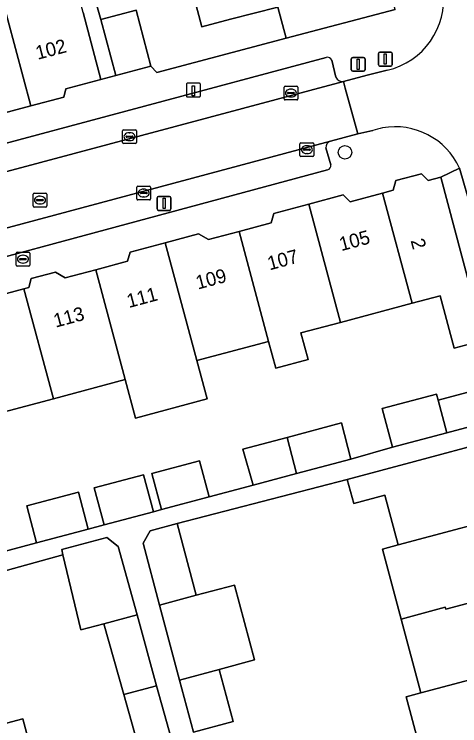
# Model space of a CAD drawing. Extents: x 162542 to 163147, y 380779 to 381521.
# Drawn here: x 162770.6 to 162802.8, y 381019 to 381070.3 of the extents above; entities that cross this region are included whole.
import ezdxf

# ---------------------------------------------------------------- set-up
doc = ezdxf.new("R2010")
doc.units = 0
for name, color, linetype in [('IMGEO_Boom', 7, 'Continuous'), ('IMGEO_Brandkraan', 7, 'Continuous'), ('IMGEO_Erf', 7, 'Continuous'), ('IMGEO_Kolk', 7, 'Continuous'), ('IMGEO_Laadpaal', 7, 'Continuous'), ('IMGEO_Lichtmast', 7, 'Continuous'), ('IMGEO_Muur', 7, 'Continuous'), ('IMGEO_Pand', 7, 'Continuous'), ('IMGEO_Pand_nummerreeks', 7, 'Continuous'), ('IMGEO_Parkeervlak_open', 7, 'Continuous'), ('IMGEO_Rijbaan_lokaal_open', 7, 'Continuous'), ('IMGEO_Rioolput', 7, 'Continuous'), ('IMGEO_Voetpad_open', 7, 'Continuous')]:
    doc.layers.add(name, color=color, linetype=linetype)

msp = doc.modelspace()

# ---------------------------------------------------------------- linework, layer by layer
at = {"layer": 'IMGEO_Boom'}
msp.add_circle((162794.494, 381060.375), 0.489, dxfattribs=at)
at = {"layer": 'IMGEO_Brandkraan'}
for p, q in [((162770.738, 381052.236), (162770.738, 381053.088)), ((162770.813, 381053.162), (162771.665, 381053.162)), ((162771.04, 381052.705), (162771.438, 381052.705)), ((162771.226, 381052.942), (162771.251, 381052.942)), ((162771.739, 381053.088), (162771.739, 381052.236)), ((162770.997, 381052.656), (162770.997, 381052.668)), ((162771.435, 381052.619), (162771.037, 381052.619)), ((162771.249, 381052.382), (162771.224, 381052.382)), ((162771.481, 381052.668), (162771.481, 381052.656)), ((162771.665, 381052.162), (162770.813, 381052.162))]:
    msp.add_line(p, q, dxfattribs=at)
for points in [[(162770.738, 381052.236), (162770.738, 381053.088)], [(162770.813, 381053.162), (162771.665, 381053.162)], [(162771.739, 381053.088), (162771.739, 381052.236)], [(162771.665, 381052.162), (162770.813, 381052.162)]]:
    msp.add_lwpolyline(points, dxfattribs=at)
for centre, radius, start, end in [((162770.815, 381053.086), 0.0765, 91.552, 178.448), ((162770.815, 381053.086), 0.0765, 91.552, 178.448), ((162771.037, 381052.665), 0.0403, 85.8775, 175.7526), ((162771.442, 381052.667), 0.0386, 1.7309, 96.639), ((162771.663, 381053.086), 0.0765, 1.552, 88.448), ((162771.663, 381053.086), 0.0765, 1.552, 88.448), ((162770.815, 381052.238), 0.0765, 181.552, 268.448), ((162770.815, 381052.238), 0.0765, 181.552, 268.448), ((162771.034, 381052.655), 0.0366, 178.938, 274.7102), ((162771.438, 381052.662), 0.043, 264.8664, 352.4533), ((162771.663, 381052.238), 0.0765, 271.552, 358.448), ((162771.663, 381052.238), 0.0765, 271.552, 358.448)]:
    msp.add_arc(centre, radius, start, end, dxfattribs=at)
for centre, major_axis, ratio, start_param, end_param in [((162771.225, 381052.662), (-0.387, 0.002), 0.722429, 4.712389, 7.853982), ((162771.25, 381052.662), (-0.39, 0.002), 0.717154, 1.570796, 4.712389)]:
    msp.add_ellipse(centre, major_axis=major_axis, ratio=ratio, start_param=start_param, end_param=end_param, dxfattribs=at)
at = {"layer": 'IMGEO_Erf'}
for points in [[(162774.056, 381079.887), (162776.859, 381069.965), (162779.405, 381070.644), (162780.482, 381066.606), (162780.903, 381066.133), (162790.25, 381068.607), (162789.654, 381070.857), (162786.215, 381069.993), (162784.155, 381069.446), (162783.526, 381071.816)], [(162804.535, 381046.81), (162802.384, 381046.237), (162801.377, 381050.022), (162799.344, 381049.481), (162794.163, 381048.103), (162791.316, 381047.346), (162791.828, 381045.42), (162789.492, 381044.799), (162788.98, 381046.725), (162783.799, 381045.346), (162784.536, 381042.573), (162779.354, 381041.194), (162778.617, 381043.968), (162773.434, 381042.59), (162768.253, 381041.212)], [(162769.237, 381031.405), (162772.228, 381032.18), (162771.516, 381034.857), (162775.24, 381035.847), (162775.952, 381033.17), (162777.1, 381033.475), (162776.388, 381036.152), (162779.95, 381037.1), (162780.662, 381034.423), (162781.246, 381034.586), (162780.551, 381037.2), (162783.989, 381038.114), (162784.684, 381035.5), (162787.869, 381036.347), (162787.108, 381038.943), (162790.307, 381039.794), (162794.231, 381040.838), (162794.926, 381038.224), (162797.923, 381039.094), (162797.182, 381041.883), (162801.098, 381042.925), (162801.215, 381042.483), (162805.355, 381043.584)], [(162800.284, 381015.954), (162798.917, 381021.069), (162799.976, 381021.363), (162798.554, 381026.681), (162797.202, 381031.738), (162798.325, 381032.038), (162797.365, 381035.632), (162795.127, 381035.034), (162794.663, 381036.768), (162782.37, 381033.574), (162783.755, 381028.398), (162786.521, 381029.138), (162787.967, 381023.733), (162785.414, 381023.049), (162786.42, 381019.291), (162783.558, 381018.525)], [(162779.972, 381016.079), (162778.524, 381021.236), (162777.088, 381026.348), (162775.416, 381025.911), (162774.127, 381031.315), (162765.392, 381028.911), (162766.804, 381023.607), (162768.122, 381018.658), (162771.235, 381019.487), (162772.661, 381014.131)]]:
    msp.add_lwpolyline(points, dxfattribs=at)
at = {"layer": 'IMGEO_Kolk'}
for p, q in [((162790.091, 381064.229), (162790.091, 381065.081)), ((162790.166, 381065.155), (162791.018, 381065.155)), ((162791.092, 381065.081), (162791.092, 381064.229)), ((162790.35, 381064.649), (162790.35, 381064.661)), ((162790.788, 381064.612), (162790.39, 381064.612)), ((162790.393, 381064.698), (162790.791, 381064.698)), ((162790.579, 381064.935), (162790.604, 381064.935)), ((162790.834, 381064.661), (162790.834, 381064.649)), ((162791.018, 381064.155), (162790.166, 381064.155)), ((162790.602, 381064.375), (162790.577, 381064.375)), ((162778.432, 381061.08), (162778.432, 381061.932)), ((162778.507, 381062.006), (162779.359, 381062.006)), ((162779.433, 381061.932), (162779.433, 381061.08)), ((162778.691, 381061.5), (162778.691, 381061.512)), ((162779.129, 381061.463), (162778.731, 381061.463)), ((162778.734, 381061.549), (162779.132, 381061.549)), ((162778.92, 381061.786), (162778.945, 381061.786)), ((162779.175, 381061.512), (162779.175, 381061.5)), ((162779.359, 381061.006), (162778.507, 381061.006)), ((162778.943, 381061.226), (162778.918, 381061.226)), ((162791.241, 381060.143), (162791.241, 381060.995)), ((162791.316, 381061.069), (162792.168, 381061.069)), ((162792.242, 381060.995), (162792.242, 381060.143)), ((162791.5, 381060.563), (162791.5, 381060.575)), ((162791.938, 381060.526), (162791.54, 381060.526)), ((162791.543, 381060.612), (162791.941, 381060.612)), ((162791.729, 381060.849), (162791.754, 381060.849)), ((162791.984, 381060.575), (162791.984, 381060.563)), ((162792.168, 381060.069), (162791.316, 381060.069)), ((162791.752, 381060.289), (162791.727, 381060.289)), ((162779.456, 381057.01), (162779.456, 381057.862)), ((162779.531, 381057.936), (162780.383, 381057.936)), ((162780.457, 381057.862), (162780.457, 381057.01)), ((162779.715, 381057.43), (162779.715, 381057.442)), ((162780.153, 381057.393), (162779.755, 381057.393)), ((162779.758, 381057.479), (162780.156, 381057.479)), ((162779.944, 381057.716), (162779.969, 381057.716)), ((162780.199, 381057.442), (162780.199, 381057.43)), ((162780.383, 381056.936), (162779.531, 381056.936)), ((162779.967, 381057.156), (162779.942, 381057.156))]:
    msp.add_line(p, q, dxfattribs=at)
for points in [[(162790.091, 381064.229), (162790.091, 381065.081)], [(162790.166, 381065.155), (162791.018, 381065.155)], [(162791.092, 381065.081), (162791.092, 381064.229)], [(162791.018, 381064.155), (162790.166, 381064.155)], [(162778.432, 381061.08), (162778.432, 381061.932)], [(162778.507, 381062.006), (162779.359, 381062.006)], [(162779.433, 381061.932), (162779.433, 381061.08)], [(162779.359, 381061.006), (162778.507, 381061.006)], [(162791.241, 381060.143), (162791.241, 381060.995)], [(162791.316, 381061.069), (162792.168, 381061.069)], [(162792.242, 381060.995), (162792.242, 381060.143)], [(162792.168, 381060.069), (162791.316, 381060.069)], [(162779.456, 381057.01), (162779.456, 381057.862)], [(162779.531, 381057.936), (162780.383, 381057.936)], [(162780.457, 381057.862), (162780.457, 381057.01)], [(162780.383, 381056.936), (162779.531, 381056.936)]]:
    msp.add_lwpolyline(points, dxfattribs=at)
for centre, radius, start, end in [((162790.168, 381065.079), 0.0765, 91.552, 178.448), ((162790.168, 381065.079), 0.0765, 91.552, 178.448), ((162791.016, 381065.079), 0.0765, 1.552, 88.448), ((162791.016, 381065.079), 0.0765, 1.552, 88.448), ((162790.39, 381064.658), 0.0403, 85.8775, 175.7526), ((162790.387, 381064.648), 0.0366, 178.938, 274.7102), ((162790.791, 381064.655), 0.043, 264.8664, 352.4533), ((162790.795, 381064.66), 0.0386, 1.7309, 96.639), ((162790.168, 381064.231), 0.0765, 181.552, 268.448), ((162790.168, 381064.231), 0.0765, 181.552, 268.448), ((162791.016, 381064.231), 0.0765, 271.552, 358.448), ((162791.016, 381064.231), 0.0765, 271.552, 358.448), ((162778.509, 381061.93), 0.0765, 91.552, 178.448), ((162778.509, 381061.93), 0.0765, 91.552, 178.448), ((162779.357, 381061.93), 0.0765, 1.552, 88.448), ((162779.357, 381061.93), 0.0765, 1.552, 88.448), ((162778.731, 381061.509), 0.0403, 85.8775, 175.7526), ((162778.728, 381061.499), 0.0366, 178.938, 274.7102), ((162779.132, 381061.506), 0.043, 264.8664, 352.4533), ((162779.136, 381061.511), 0.0386, 1.7309, 96.639), ((162778.509, 381061.082), 0.0765, 181.552, 268.448), ((162778.509, 381061.082), 0.0765, 181.552, 268.448), ((162779.357, 381061.082), 0.0765, 271.552, 358.448), ((162779.357, 381061.082), 0.0765, 271.552, 358.448), ((162791.318, 381060.993), 0.0765, 91.552, 178.448), ((162791.318, 381060.993), 0.0765, 91.552, 178.448), ((162792.166, 381060.993), 0.0765, 1.552, 88.448), ((162792.166, 381060.993), 0.0765, 1.552, 88.448), ((162791.54, 381060.572), 0.0403, 85.8775, 175.7526), ((162791.537, 381060.562), 0.0366, 178.938, 274.7102), ((162791.941, 381060.569), 0.043, 264.8664, 352.4533), ((162791.945, 381060.574), 0.0386, 1.7309, 96.639), ((162791.318, 381060.145), 0.0765, 181.552, 268.448), ((162791.318, 381060.145), 0.0765, 181.552, 268.448), ((162792.166, 381060.145), 0.0765, 271.552, 358.448), ((162792.166, 381060.145), 0.0765, 271.552, 358.448), ((162779.533, 381057.86), 0.0765, 91.552, 178.448), ((162779.533, 381057.86), 0.0765, 91.552, 178.448), ((162780.381, 381057.86), 0.0765, 1.552, 88.448), ((162780.381, 381057.86), 0.0765, 1.552, 88.448), ((162779.755, 381057.439), 0.0403, 85.8775, 175.7526), ((162779.752, 381057.429), 0.0366, 178.938, 274.7102), ((162780.156, 381057.436), 0.043, 264.8664, 352.4533), ((162780.16, 381057.441), 0.0386, 1.7309, 96.639), ((162779.533, 381057.012), 0.0765, 181.552, 268.448), ((162779.533, 381057.012), 0.0765, 181.552, 268.448), ((162780.381, 381057.012), 0.0765, 271.552, 358.448), ((162780.381, 381057.012), 0.0765, 271.552, 358.448)]:
    msp.add_arc(centre, radius, start, end, dxfattribs=at)
for centre, major_axis, ratio, start_param, end_param in [((162790.578, 381064.655), (-0.387, 0.002), 0.722429, 4.712389, 7.853982), ((162790.603, 381064.655), (-0.39, 0.002), 0.717154, 1.570796, 4.712389), ((162778.919, 381061.506), (-0.387, 0.002), 0.722429, 4.712389, 7.853982), ((162778.944, 381061.506), (-0.39, 0.002), 0.717154, 1.570796, 4.712389), ((162791.728, 381060.569), (-0.387, 0.002), 0.722429, 4.712389, 7.853982), ((162791.753, 381060.569), (-0.39, 0.002), 0.717154, 1.570796, 4.712389), ((162779.943, 381057.436), (-0.387, 0.002), 0.722429, 4.712389, 7.853982), ((162779.968, 381057.436), (-0.39, 0.002), 0.717154, 1.570796, 4.712389)]:
    msp.add_ellipse(centre, major_axis=major_axis, ratio=ratio, start_param=start_param, end_param=end_param, dxfattribs=at)
at = {"layer": 'IMGEO_Laadpaal'}
for p, q in [((162783.05, 381065.288), (162783.05, 381064.447)), ((162783.05, 381065.288), (162783.05, 381064.447)), ((162783.966, 381065.372), (162783.125, 381065.372)), ((162783.966, 381065.372), (162783.125, 381065.372)), ((162784.05, 381064.456), (162784.05, 381065.297)), ((162784.05, 381064.456), (162784.05, 381065.297)), ((162783.134, 381064.372), (162783.975, 381064.372)), ((162783.134, 381064.372), (162783.975, 381064.372))]:
    msp.add_line(p, q, dxfattribs=at)
msp.add_lwpolyline([(162783.465, 381065.185), (162783.625, 381065.185), (162783.625, 381064.452), (162783.465, 381064.452), (162783.465, 381065.185)], dxfattribs=at)
for centre, start, end in [((162783.128, 381065.294), 92.4484, 184.2845), ((162783.128, 381065.294), 92.4484, 184.2845), ((162783.972, 381065.294), 2.4484, 94.2845), ((162783.972, 381065.294), 2.4484, 94.2845), ((162783.128, 381064.45), 182.4484, 274.2845), ((162783.128, 381064.45), 182.4484, 274.2845), ((162783.972, 381064.45), 272.4484, 4.2845), ((162783.972, 381064.45), 272.4484, 4.2845)]:
    msp.add_arc(centre, 0.0779, start, end, dxfattribs=at)
at = {"layer": 'IMGEO_Lichtmast'}
for p, q in [((162797.006, 381067.603), (162797.796, 381067.603)), ((162797.796, 381067.603), (162797.006, 381067.603)), ((162794.951, 381066.326), (162794.951, 381067.126)), ((162794.951, 381067.126), (162794.951, 381066.326)), ((162795.051, 381067.226), (162795.841, 381067.226)), ((162795.841, 381067.226), (162795.051, 381067.226)), ((162795.941, 381067.126), (162795.941, 381066.326)), ((162795.941, 381066.326), (162795.941, 381067.126)), ((162796.906, 381066.703), (162796.906, 381067.503)), ((162796.906, 381067.503), (162796.906, 381066.703)), ((162797.896, 381067.503), (162797.896, 381066.703)), ((162797.896, 381066.703), (162797.896, 381067.503)), ((162797.796, 381066.603), (162797.006, 381066.603)), ((162797.006, 381066.603), (162797.796, 381066.603)), ((162795.841, 381066.226), (162795.051, 381066.226)), ((162795.051, 381066.226), (162795.841, 381066.226)), ((162780.932, 381056.288), (162780.932, 381057.088)), ((162780.932, 381057.088), (162780.932, 381056.288)), ((162781.032, 381057.188), (162781.822, 381057.188)), ((162781.822, 381057.188), (162781.032, 381057.188)), ((162781.922, 381057.088), (162781.922, 381056.288)), ((162781.922, 381056.288), (162781.922, 381057.088)), ((162781.822, 381056.188), (162781.032, 381056.188)), ((162781.032, 381056.188), (162781.822, 381056.188))]:
    msp.add_line(p, q, dxfattribs=at)
for points in [[(162795.371, 381067.101), (162795.521, 381067.101), (162795.521, 381066.351), (162795.371, 381066.351), (162795.371, 381067.101)], [(162797.326, 381067.478), (162797.476, 381067.478), (162797.476, 381066.728), (162797.326, 381066.728), (162797.326, 381067.478)], [(162781.352, 381057.063), (162781.502, 381057.063), (162781.502, 381056.313), (162781.352, 381056.313), (162781.352, 381057.063)]]:
    msp.add_lwpolyline(points, dxfattribs=at)
for centre, start, end in [((162797.006, 381067.503), 90, 180), ((162797.006, 381067.503), 90, 180), ((162797.796, 381067.503), 0, 90), ((162797.796, 381067.503), 360, 90), ((162795.051, 381067.126), 90, 180), ((162795.051, 381067.126), 90, 180), ((162795.841, 381067.126), 0, 90), ((162795.841, 381067.126), 360, 90), ((162797.006, 381066.703), 180, 270), ((162797.006, 381066.703), 180, 270), ((162797.796, 381066.703), 270, 0), ((162797.796, 381066.703), 270, 0), ((162795.051, 381066.326), 180, 270), ((162795.051, 381066.326), 180, 270), ((162795.841, 381066.326), 270, 0), ((162795.841, 381066.326), 270, 0), ((162781.032, 381057.088), 90, 180), ((162781.032, 381057.088), 90, 180), ((162781.822, 381057.088), 0, 90), ((162781.822, 381057.088), 360, 90), ((162781.032, 381056.288), 180, 270), ((162781.032, 381056.288), 180, 270), ((162781.822, 381056.288), 270, 0), ((162781.822, 381056.288), 270, 0)]:
    msp.add_arc(centre, 0.1, start, end, dxfattribs=at)
at = {"layer": 'IMGEO_Muur'}
msp.add_lwpolyline([(162790.25, 381068.607), (162780.903, 381066.133), (162780.482, 381066.606)], dxfattribs=at)
at = {"layer": 'IMGEO_Pand'}
for points in [[(162771.805, 381063.723), (162774.182, 381064.357), (162774.346, 381064.969), (162776.867, 381065.641), (162775.579, 381070.473), (162774.793, 381073.421), (162773.82, 381077.07), (162768.611, 381075.681), (162769.584, 381072.032)], [(162796.857, 381075.377), (162789.775, 381073.478), (162789.181, 381073.318), (162788.962, 381073.26), (162783.526, 381071.816), (162784.155, 381069.446), (162786.215, 381069.993), (162789.654, 381070.857), (162790.25, 381068.607), (162798.117, 381070.679)], [(162769.584, 381072.032), (162764.213, 381070.599), (162766.025, 381063.843), (162765.878, 381063.804), (162766.136, 381062.838), (162768.598, 381063.494), (162769.091, 381063), (162771.805, 381063.723)], [(162780.482, 381066.606), (162779.405, 381070.644), (162776.859, 381069.965), (162777.935, 381065.927)], [(162799.344, 381049.481), (162801.377, 381050.022), (162802.384, 381046.237), (162804.535, 381046.81), (162801.405, 381058.58), (162800.504, 381058.341), (162800.018, 381058.829), (162798.163, 381058.335), (162797.974, 381057.636), (162797.213, 381057.434)], [(162794.163, 381048.103), (162799.344, 381049.481), (162797.213, 381057.434), (162794.859, 381056.808), (162794.367, 381057.302), (162791.876, 381056.639)], [(162791.876, 381056.639), (162789.36, 381055.97), (162789.174, 381055.281), (162786.853, 381054.664), (162788.98, 381046.725), (162789.492, 381044.799), (162791.828, 381045.42), (162791.316, 381047.346), (162794.163, 381048.103)], [(162788.98, 381046.725), (162786.853, 381054.664), (162784.629, 381054.072), (162783.91, 381054.49), (162781.519, 381053.854), (162783.799, 381045.346)], [(162778.617, 381043.968), (162779.354, 381041.194), (162784.536, 381042.573), (162783.799, 381045.346), (162781.519, 381053.854), (162778.979, 381053.178), (162778.8, 381052.514), (162776.492, 381051.9)], [(162778.617, 381043.968), (162776.492, 381051.9), (162774.292, 381051.315), (162773.579, 381051.728), (162771.841, 381051.266), (162771.664, 381050.61), (162771.311, 381050.516), (162773.434, 381042.59)], [(162765.984, 381049.682), (162768.253, 381041.212), (162773.434, 381042.59), (162771.311, 381050.516), (162769.04, 381049.912), (162768.58, 381050.373)], [(162801.848, 381040.138), (162805.979, 381041.236), (162805.355, 381043.584), (162801.215, 381042.483)], [(162801.848, 381040.138), (162801.215, 381042.483), (162801.098, 381042.925), (162797.182, 381041.883), (162797.923, 381039.094)], [(162790.307, 381039.794), (162791.002, 381037.18), (162794.926, 381038.224), (162794.231, 381040.838)], [(162798.325, 381032.038), (162807.74, 381034.555), (162806.315, 381039.883), (162801.485, 381038.592), (162799.525, 381038.068), (162794.663, 381036.768), (162795.127, 381035.034), (162797.365, 381035.632)], [(162790.307, 381039.794), (162787.108, 381038.943), (162787.869, 381036.347), (162791.002, 381037.18)], [(162781.246, 381034.586), (162784.684, 381035.5), (162783.989, 381038.114), (162780.551, 381037.2)], [(162777.1, 381033.475), (162780.662, 381034.423), (162779.95, 381037.1), (162776.388, 381036.152)], [(162772.228, 381032.18), (162775.952, 381033.17), (162775.24, 381035.847), (162771.516, 381034.857)], [(162798.554, 381026.681), (162801.73, 381027.542), (162801.769, 381027.398), (162808.109, 381029.095), (162808.147, 381028.951), (162809.165, 381029.223), (162807.74, 381034.555), (162798.325, 381032.038), (162797.202, 381031.738)], [(162782.37, 381033.574), (162780.425, 381033.054), (162779.908, 381032.162), (162781.105, 381027.689), (162783.755, 381028.398)], [(162778.123, 381031.924), (162777.287, 381032.58), (162774.034, 381031.703), (162774.127, 381031.315), (162775.416, 381025.911), (162777.088, 381026.348), (162779.484, 381026.987)], [(162783.755, 381028.398), (162781.105, 381027.689), (162782.552, 381022.284), (162785.414, 381023.049), (162787.967, 381023.733), (162786.521, 381029.138)], [(162798.554, 381026.681), (162799.976, 381021.363), (162809.505, 381023.876), (162808.147, 381028.951), (162808.109, 381029.095), (162801.769, 381027.398), (162801.73, 381027.542)], [(162777.088, 381026.348), (162778.524, 381021.236), (162780.894, 381021.869), (162779.484, 381026.987)], [(162810.868, 381018.786), (162809.505, 381023.876), (162799.976, 381021.363), (162798.917, 381021.069), (162800.284, 381015.954), (162804.097, 381016.973)], [(162785.414, 381023.049), (162782.552, 381022.284), (162783.558, 381018.525), (162786.42, 381019.291)], [(162780.894, 381021.869), (162778.524, 381021.236), (162779.972, 381016.079), (162782.318, 381016.705)], [(162771.235, 381019.487), (162768.122, 381018.658), (162767.564, 381018.509), (162765.096, 381017.852), (162765.147, 381017.666), (162757.964, 381015.749), (162758.011, 381015.58), (162758.966, 381011.993), (162760.394, 381012.373), (162760.77, 381010.962), (162772.661, 381014.131)]]:
    msp.add_lwpolyline(points, close=True, dxfattribs=at)
at = {"layer": 'IMGEO_Parkeervlak_open'}
for points in [[(162793.143, 381067.232), (162766.863, 381060.195)], [(162793.835, 381065.803), (162793.536, 381067.033)], [(162730.046, 381048.353), (162732.138, 381048.912), (162740.764, 381051.202), (162748.957, 381053.378), (162755.459, 381055.104), (162794.388, 381065.492)], [(162793.438, 381061.177), (162749.869, 381049.501)], [(162793.467, 381059.48), (162793.114, 381060.697)], [(162751.104, 381047.757), (162793.241, 381059.11)]]:
    msp.add_lwpolyline(points, dxfattribs=at)
for centre, radius, start, end in [((162793.218, 381066.892), 0.348, 23.9193, 102.3689), ((162794.314, 381066.008), 0.521, 203.1447, 278.1496), ((162793.563, 381060.743), 0.451, 106.0713, 185.89), ((162793.162, 381059.412), 0.313, 284.698, 12.4679)]:
    msp.add_arc(centre, radius, start, end, dxfattribs=at)
at = {"layer": 'IMGEO_Rijbaan_lokaal_open'}
for points in [[(162797.531, 381066.303), (162796.104, 381065.935), (162794.388, 381065.492), (162794.501, 381065.002), (162795.429, 381061.72), (162796.501, 381061.953)], [(162802.766, 381059.241), (162803.658, 381056.146), (162807.705, 381057.197), (162807.647, 381057.415), (162807.233, 381058.879)]]:
    msp.add_lwpolyline(points, dxfattribs=at)
msp.add_lwpolyline([(162793.438, 381061.177), (162795.429, 381061.72), (162794.501, 381065.002), (162794.388, 381065.492), (162755.459, 381055.104), (162748.957, 381053.378), (162749.869, 381049.501)], close=True, dxfattribs=at)
for centre, radius, start, end in [((162796.373, 381071.413), 5.239, 282.7716, 7.263), ((162798.153, 381056.996), 5.226, 100.3561, 108.4338), ((162798.126, 381057.114), 5.104, 24.6286, 100.2933)]:
    msp.add_arc(centre, radius, start, end, dxfattribs=at)
at = {"layer": 'IMGEO_Rioolput'}
for p, q in [((162771.966, 381056.503), (162771.966, 381057.355)), ((162772.041, 381057.429), (162772.893, 381057.429)), ((162772.967, 381057.355), (162772.967, 381056.503)), ((162772.225, 381056.923), (162772.225, 381056.935)), ((162772.663, 381056.886), (162772.265, 381056.886)), ((162772.268, 381056.972), (162772.666, 381056.972)), ((162772.454, 381057.209), (162772.479, 381057.209)), ((162772.709, 381056.935), (162772.709, 381056.923)), ((162772.893, 381056.429), (162772.041, 381056.429)), ((162772.477, 381056.649), (162772.452, 381056.649))]:
    msp.add_line(p, q, dxfattribs=at)
for points in [[(162771.966, 381056.503), (162771.966, 381057.355)], [(162772.041, 381057.429), (162772.893, 381057.429)], [(162772.967, 381057.355), (162772.967, 381056.503)], [(162772.893, 381056.429), (162772.041, 381056.429)]]:
    msp.add_lwpolyline(points, dxfattribs=at)
for centre, radius, start, end in [((162772.043, 381057.353), 0.0765, 91.552, 178.448), ((162772.043, 381057.353), 0.0765, 91.552, 178.448), ((162772.891, 381057.353), 0.0765, 1.552, 88.448), ((162772.891, 381057.353), 0.0765, 1.552, 88.448), ((162772.265, 381056.932), 0.0403, 85.8775, 175.7526), ((162772.262, 381056.922), 0.0366, 178.938, 274.7102), ((162772.666, 381056.929), 0.043, 264.8664, 352.4533), ((162772.67, 381056.934), 0.0386, 1.7309, 96.639), ((162772.043, 381056.505), 0.0765, 181.552, 268.448), ((162772.043, 381056.505), 0.0765, 181.552, 268.448), ((162772.891, 381056.505), 0.0765, 271.552, 358.448), ((162772.891, 381056.505), 0.0765, 271.552, 358.448)]:
    msp.add_arc(centre, radius, start, end, dxfattribs=at)
for centre, major_axis, ratio, start_param, end_param in [((162772.453, 381056.929), (-0.387, 0.002), 0.722429, 4.712389, 7.853982), ((162772.478, 381056.929), (-0.39, 0.002), 0.717154, 1.570796, 4.712389)]:
    msp.add_ellipse(centre, major_axis=major_axis, ratio=ratio, start_param=start_param, end_param=end_param, dxfattribs=at)
at = {"layer": 'IMGEO_Voetpad_open'}
for points in [[(162775.579, 381070.473), (162776.867, 381065.641), (162777.935, 381065.927), (162776.859, 381069.965), (162774.056, 381079.887)], [(162798.117, 381070.679), (162790.25, 381068.607), (162780.903, 381066.133), (162780.482, 381066.606), (162777.935, 381065.927), (162776.867, 381065.641), (162774.346, 381064.969), (162774.182, 381064.357), (162771.805, 381063.723), (162769.091, 381063)], [(162766.863, 381060.195), (162793.143, 381067.232)], [(162793.536, 381067.033), (162793.835, 381065.803)], [(162794.388, 381065.492), (162796.104, 381065.935), (162797.531, 381066.303)], [(162796.501, 381061.953), (162795.429, 381061.72), (162793.438, 381061.177)], [(162793.114, 381060.697), (162793.467, 381059.48)], [(162793.241, 381059.11), (162751.104, 381047.757)], [(162769.04, 381049.912), (162771.311, 381050.516), (162771.664, 381050.61), (162771.841, 381051.266), (162773.579, 381051.728), (162774.292, 381051.315), (162776.492, 381051.9), (162778.8, 381052.514), (162778.979, 381053.178), (162781.519, 381053.854), (162783.91, 381054.49), (162784.629, 381054.072), (162786.853, 381054.664), (162789.174, 381055.281), (162789.36, 381055.97), (162791.876, 381056.639), (162794.367, 381057.302), (162794.859, 381056.808), (162797.213, 381057.434), (162797.974, 381057.636), (162798.163, 381058.335), (162800.018, 381058.829), (162800.504, 381058.341), (162801.405, 381058.58), (162802.766, 381059.241)], [(162803.658, 381056.146), (162802.766, 381059.241), (162801.405, 381058.58), (162804.535, 381046.81)], [(162805.979, 381041.236), (162801.848, 381040.138), (162797.923, 381039.094), (162794.926, 381038.224), (162791.002, 381037.18), (162787.869, 381036.347), (162784.684, 381035.5), (162781.246, 381034.586), (162780.662, 381034.423), (162777.1, 381033.475), (162775.952, 381033.17), (162772.228, 381032.18), (162769.237, 381031.405)], [(162783.558, 381018.525), (162782.552, 381022.284), (162781.105, 381027.689), (162779.908, 381032.162), (162780.425, 381033.054), (162782.37, 381033.574), (162794.663, 381036.768), (162799.525, 381038.068), (162801.485, 381038.592), (162806.315, 381039.883)], [(162765.392, 381028.911), (162774.127, 381031.315), (162774.034, 381031.703), (162777.287, 381032.58), (162778.123, 381031.924), (162779.484, 381026.987), (162780.894, 381021.869), (162782.318, 381016.705)]]:
    msp.add_lwpolyline(points, dxfattribs=at)
for centre, radius, start, end in [((162796.373, 381071.413), 5.239, 282.7716, 7.263), ((162793.218, 381066.892), 0.348, 23.9193, 102.3689), ((162794.314, 381066.008), 0.521, 203.1447, 278.1496), ((162798.153, 381056.996), 5.226, 100.3561, 108.4338), ((162798.126, 381057.114), 5.104, 24.6286, 100.2933), ((162793.563, 381060.743), 0.451, 106.0713, 185.89), ((162793.162, 381059.412), 0.313, 284.698, 12.4679)]:
    msp.add_arc(centre, radius, start, end, dxfattribs=at)

# ---------------------------------------------------------------- texts
at = {"layer": 'IMGEO_Pand_nummerreeks'}
for s, rotation, p in [('102', 14.6389, (162772.3, 381067.053)), ('105', 14.988, (162794.228, 381053.239)), ('2', 284.892, (162799.225, 381054.012)), ('107', 14.988, (162789.048, 381051.852)), ('109', 14.988, (162783.869, 381050.466)), ('111', 14.988, (162778.887, 381049.132)), ('113', 14.988, (162773.599, 381047.716))]:
    msp.add_text(s, height=1, rotation=rotation, dxfattribs=at).set_placement(p)

doc.saveas('drawing.dxf')
